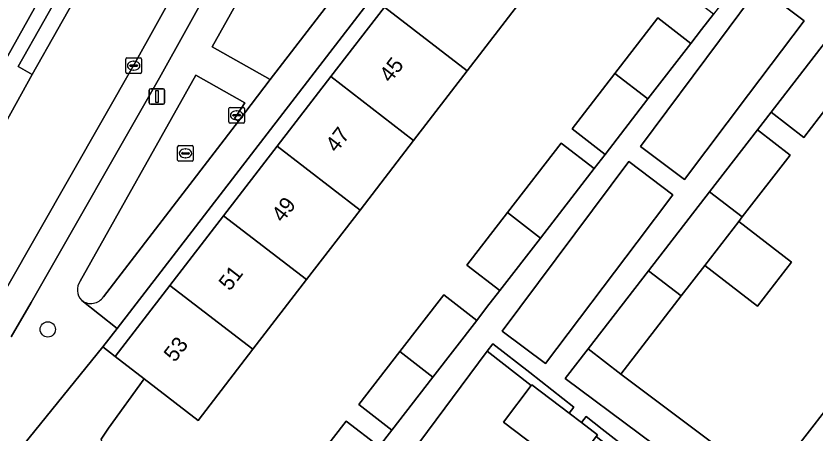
# Model space of a CAD drawing. Extents: x 159039 to 160102, y 381214 to 382524.
# Drawn here: x 159185.6 to 159236.7, y 381504.4 to 381531.1 of the extents above; entities that cross this region are included whole.
import ezdxf

# ---------------------------------------------------------------- set-up
doc = ezdxf.new("R2010")
doc.units = 0
for name, color, linetype in [('IMGEO_Boom', 7, 'Continuous'), ('IMGEO_Erf', 7, 'Continuous'), ('IMGEO_Groenvoorziening', 7, 'Continuous'), ('IMGEO_Kolk', 7, 'Continuous'), ('IMGEO_Lichtmast', 7, 'Continuous'), ('IMGEO_Pand', 7, 'Continuous'), ('IMGEO_Pand_nummerreeks', 7, 'Continuous'), ('IMGEO_Parkeervlak_open', 7, 'Continuous'), ('IMGEO_Rijbaan_lokaal_open', 7, 'Continuous'), ('IMGEO_Rioolput', 7, 'Continuous'), ('IMGEO_Voetpad_open', 7, 'Continuous')]:
    doc.layers.add(name, color=color, linetype=linetype)

msp = doc.modelspace()

# ---------------------------------------------------------------- linework, layer by layer
at = {"layer": 'IMGEO_Boom'}
msp.add_circle((159187.608, 381511.034), 0.489, dxfattribs=at)
at = {"layer": 'IMGEO_Erf'}
for points in [[(159225.401, 381554.424), (159192.033, 381511.095), (159191.13, 381509.922), (159191.91, 381509.302), (159195.414, 381513.848), (159198.846, 381518.299), (159202.279, 381522.752), (159205.711, 381527.204), (159209.143, 381531.656)], [(159212.926, 381513.239), (159215.038, 381511.61), (159215.669, 381512.427), (159216.508, 381513.514), (159214.396, 381515.142), (159216.994, 381518.504), (159220.431, 381522.952), (159222.542, 381521.324), (159223.24, 381522.227), (159221.129, 381523.855), (159223.869, 381527.4), (159226.617, 381530.956), (159228.727, 381529.33), (159229.415, 381530.221), (159230.179, 381531.21), (159228.069, 381532.836), (159230.742, 381536.295), (159233.31, 381539.618), (159235.418, 381537.992), (159236.286, 381539.116), (159234.178, 381540.742), (159237.678, 381545.272)], [(159173.453, 381507.955), (159176.296, 381513.115), (159179.604, 381518.88), (159180.292, 381520.169), (159180.696, 381520.785), (159188.162, 381534.124)], [(159217.857, 381532.034), (159214.429, 381527.58), (159211.001, 381523.125), (159207.573, 381518.67), (159204.145, 381514.215), (159200.717, 381509.76), (159197.216, 381505.211), (159193.761, 381507.875), (159191.482, 381504.708), (159191.012, 381504.016)], [(159233.651, 381501.109), (159237.416, 381505.981), (159241.32, 381511.034), (159245.252, 381516.123), (159243.127, 381517.765), (159246.961, 381522.727), (159250.649, 381527.499), (159252.774, 381525.857), (159256.666, 381530.894)], [(159237.43, 381525.232), (159235.947, 381523.313), (159233.855, 381524.929), (159232.982, 381523.799), (159235.074, 381522.183), (159232.015, 381518.224), (159231.797, 381517.942), (159235.165, 381515.341), (159232.985, 381512.52), (159229.618, 381515.122), (159228.111, 381513.172), (159224.253, 381508.179), (159231.589, 381502.66)], [(159203.239, 381500.702), (159206.684, 381505.16), (159208.797, 381503.531), (159209.615, 381504.59), (159207.503, 381506.221), (159210.121, 381509.609), (159212.926, 381513.239)], [(159232.559, 381496.471), (159231.636, 381497.192), (159230.56, 381498.032), (159229.092, 381496.063), (159228.937, 381495.854), (159225.509, 381498.452), (159222.066, 381501.061), (159222.241, 381501.296), (159223.764, 381503.337), (159222.679, 381504.184), (159221.149, 381502.131), (159220.97, 381501.891), (159216.745, 381505.093), (159218.518, 381507.433), (159215.703, 381509.632), (159210.768, 381503.013), (159203.221, 381492.897), (159214.857, 381484.15), (159222.203, 381478.451)]]:
    msp.add_lwpolyline(points, dxfattribs=at)
msp.add_arc((159182.126, 381523.448), 17.751, 60.4649, 199.9506, dxfattribs=at)
at = {"layer": 'IMGEO_Groenvoorziening'}
for points in [[(159211.449, 381539.519), (159211.235, 381539.689), (159211.37, 381539.861), (159211.764, 381540.468), (159206.227, 381543.609), (159198.115, 381529.116), (159201.832, 381527.029)], [(159235.973, 381530.774), (159233.084, 381532.954), (159230.557, 381529.518), (159225.496, 381522.744), (159228.311, 381520.62), (159232.419, 381526.063)], [(159227.577, 381519.646), (159224.766, 381521.767), (159216.66, 381510.915), (159219.428, 381508.846), (159225.296, 381516.623)], [(159218.428, 381508.265), (159216.072, 381510.105), (159215.703, 381509.632), (159218.518, 381507.433), (159218.556, 381507.483), (159220.944, 381505.673), (159221.248, 381506.063)], [(159224.253, 381508.179), (159222.161, 381509.796), (159220.696, 381507.9), (159230.193, 381500.805), (159231.589, 381502.66)], [(159223.048, 381504.657), (159222.031, 381505.451), (159221.736, 381505.073), (159222.762, 381504.295), (159222.679, 381504.184), (159223.764, 381503.337), (159223.859, 381503.465), (159224.594, 381502.908), (159224.857, 381503.245)]]:
    msp.add_lwpolyline(points, close=True, dxfattribs=at)
for points in [[(159199.8, 381524.351), (159199.555, 381524.522), (159199.686, 381524.729), (159200.197, 381525.522), (159197.07, 381527.304), (159189.668, 381514.114)], [(159191.162, 381513.114), (159199.8, 381524.351)], [(159189.761, 381512.901), (159189.786, 381512.882)]]:
    msp.add_lwpolyline(points, dxfattribs=at)
for centre, radius, start, end in [((159182.126, 381523.448), 17.751, 60.4649, 199.9506), ((159190.465, 381513.565), 0.968, 145.4294, 223.3391), ((159190.363, 381513.658), 0.967, 233.3618, 325.7789)]:
    msp.add_arc(centre, radius, start, end, dxfattribs=at)
at = {"layer": 'IMGEO_Kolk'}
for p, q in [((159192.593, 381527.479), (159192.593, 381528.331)), ((159192.668, 381528.405), (159193.52, 381528.405)), ((159193.594, 381528.331), (159193.594, 381527.479)), ((159192.852, 381527.899), (159192.852, 381527.911)), ((159193.29, 381527.862), (159192.892, 381527.862)), ((159192.895, 381527.948), (159193.293, 381527.948)), ((159193.081, 381528.185), (159193.106, 381528.185)), ((159193.336, 381527.911), (159193.336, 381527.899)), ((159193.52, 381527.405), (159192.668, 381527.405)), ((159193.104, 381527.625), (159193.079, 381527.625)), ((159199.186, 381524.303), (159199.186, 381525.155)), ((159199.261, 381525.229), (159200.113, 381525.229)), ((159200.187, 381525.155), (159200.187, 381524.303)), ((159199.445, 381524.723), (159199.445, 381524.735)), ((159199.883, 381524.686), (159199.485, 381524.686)), ((159199.488, 381524.772), (159199.886, 381524.772)), ((159199.674, 381525.009), (159199.699, 381525.009)), ((159199.929, 381524.735), (159199.929, 381524.723)), ((159200.113, 381524.229), (159199.261, 381524.229)), ((159199.697, 381524.449), (159199.672, 381524.449))]:
    msp.add_line(p, q, dxfattribs=at)
for points in [[(159192.593, 381527.479), (159192.593, 381528.331)], [(159192.668, 381528.405), (159193.52, 381528.405)], [(159193.594, 381528.331), (159193.594, 381527.479)], [(159193.52, 381527.405), (159192.668, 381527.405)], [(159199.186, 381524.303), (159199.186, 381525.155)], [(159199.261, 381525.229), (159200.113, 381525.229)], [(159200.187, 381525.155), (159200.187, 381524.303)], [(159200.113, 381524.229), (159199.261, 381524.229)]]:
    msp.add_lwpolyline(points, dxfattribs=at)
for centre, radius, start, end in [((159192.67, 381528.329), 0.0765, 91.552, 178.448), ((159192.67, 381528.329), 0.0765, 91.552, 178.448), ((159193.518, 381528.329), 0.0765, 1.552, 88.448), ((159193.518, 381528.329), 0.0765, 1.552, 88.448), ((159192.892, 381527.908), 0.0403, 85.8775, 175.7526), ((159192.889, 381527.898), 0.0366, 178.938, 274.7102), ((159193.293, 381527.905), 0.043, 264.8664, 352.4533), ((159193.297, 381527.91), 0.0386, 1.7309, 96.639), ((159192.67, 381527.481), 0.0765, 181.552, 268.448), ((159192.67, 381527.481), 0.0765, 181.552, 268.448), ((159193.518, 381527.481), 0.0765, 271.552, 358.448), ((159193.518, 381527.481), 0.0765, 271.552, 358.448), ((159199.263, 381525.153), 0.0765, 91.552, 178.448), ((159199.263, 381525.153), 0.0765, 91.552, 178.448), ((159200.111, 381525.153), 0.0765, 1.552, 88.448), ((159200.111, 381525.153), 0.0765, 1.552, 88.448), ((159199.485, 381524.732), 0.0403, 85.8775, 175.7526), ((159199.482, 381524.722), 0.0366, 178.938, 274.7102), ((159199.886, 381524.729), 0.043, 264.8664, 352.4533), ((159199.89, 381524.734), 0.0386, 1.7309, 96.639), ((159199.263, 381524.305), 0.0765, 181.552, 268.448), ((159199.263, 381524.305), 0.0765, 181.552, 268.448), ((159200.111, 381524.305), 0.0765, 271.552, 358.448), ((159200.111, 381524.305), 0.0765, 271.552, 358.448)]:
    msp.add_arc(centre, radius, start, end, dxfattribs=at)
for centre, major_axis, ratio, start_param, end_param in [((159193.08, 381527.905), (-0.387, 0.002), 0.722429, 4.712389, 7.853982), ((159193.105, 381527.905), (-0.39, 0.002), 0.717154, 1.570796, 4.712389), ((159199.673, 381524.729), (-0.387, 0.002), 0.722429, 4.712389, 7.853982), ((159199.698, 381524.729), (-0.39, 0.002), 0.717154, 1.570796, 4.712389)]:
    msp.add_ellipse(centre, major_axis=major_axis, ratio=ratio, start_param=start_param, end_param=end_param, dxfattribs=at)
at = {"layer": 'IMGEO_Lichtmast'}
for p, q in [((159194.088, 381525.533), (159194.088, 381526.333)), ((159194.088, 381526.333), (159194.088, 381525.533)), ((159194.188, 381526.433), (159194.978, 381526.433)), ((159194.978, 381526.433), (159194.188, 381526.433)), ((159195.078, 381526.333), (159195.078, 381525.533)), ((159195.078, 381525.533), (159195.078, 381526.333)), ((159194.978, 381525.433), (159194.188, 381525.433)), ((159194.188, 381525.433), (159194.978, 381525.433))]:
    msp.add_line(p, q, dxfattribs=at)
msp.add_lwpolyline([(159194.508, 381526.308), (159194.658, 381526.308), (159194.658, 381525.558), (159194.508, 381525.558), (159194.508, 381526.308)], dxfattribs=at)
for centre, start, end in [((159194.188, 381526.333), 90, 180), ((159194.188, 381526.333), 90, 180), ((159194.978, 381526.333), 0, 90), ((159194.978, 381526.333), 360, 90), ((159194.188, 381525.533), 180, 270), ((159194.188, 381525.533), 180, 270), ((159194.978, 381525.533), 270, 0), ((159194.978, 381525.533), 270, 0)]:
    msp.add_arc(centre, 0.1, start, end, dxfattribs=at)
at = {"layer": 'IMGEO_Pand'}
for points in [[(159217.857, 381532.034), (159212.574, 381536.106), (159209.143, 381531.656), (159214.429, 381527.58)], [(159211.001, 381523.125), (159214.429, 381527.58), (159209.143, 381531.656), (159205.711, 381527.204)], [(159228.727, 381529.33), (159226.617, 381530.956), (159223.869, 381527.4), (159225.979, 381525.774)], [(159241.687, 381526.801), (159239.781, 381528.274), (159237.689, 381529.891), (159233.855, 381524.929), (159235.947, 381523.313), (159237.43, 381525.232), (159239.335, 381523.759)], [(159207.573, 381518.67), (159211.001, 381523.125), (159205.711, 381527.204), (159202.279, 381522.752)], [(159225.979, 381525.774), (159223.869, 381527.4), (159221.129, 381523.855), (159223.24, 381522.227)], [(159235.074, 381522.183), (159232.982, 381523.799), (159229.923, 381519.841), (159232.015, 381518.224)], [(159207.573, 381518.67), (159202.279, 381522.752), (159198.846, 381518.299), (159204.145, 381514.215)], [(159219.106, 381516.876), (159222.542, 381521.324), (159220.431, 381522.952), (159216.994, 381518.504)], [(159231.797, 381517.942), (159232.015, 381518.224), (159229.923, 381519.841), (159226.019, 381514.788), (159228.111, 381513.172), (159229.618, 381515.122)], [(159219.106, 381516.876), (159216.994, 381518.504), (159214.396, 381515.142), (159216.508, 381513.514)], [(159195.414, 381513.848), (159200.717, 381509.76), (159204.145, 381514.215), (159198.846, 381518.299)], [(159231.797, 381517.942), (159229.618, 381515.122), (159232.985, 381512.52), (159235.165, 381515.341)], [(159228.111, 381513.172), (159226.019, 381514.788), (159222.161, 381509.796), (159224.253, 381508.179)], [(159195.414, 381513.848), (159191.91, 381509.302), (159193.761, 381507.875), (159197.216, 381505.211), (159200.717, 381509.76)], [(159215.038, 381511.61), (159212.926, 381513.239), (159210.121, 381509.609), (159212.234, 381507.981)], [(159212.234, 381507.981), (159210.121, 381509.609), (159207.503, 381506.221), (159209.615, 381504.59)], [(159220.944, 381505.673), (159218.556, 381507.483), (159218.518, 381507.433), (159216.745, 381505.093), (159220.97, 381501.891), (159221.149, 381502.131), (159222.679, 381504.184), (159222.762, 381504.295), (159221.736, 381505.073)], [(159237.416, 381505.981), (159233.651, 381501.109), (159235.088, 381500), (159239.061, 381496.992), (159241.375, 381500), (159242.785, 381501.832)], [(159208.797, 381503.531), (159206.684, 381505.16), (159203.239, 381500.702), (159204.147, 381500), (159205.351, 381499.07), (159206.069, 381500)]]:
    msp.add_lwpolyline(points, close=True, dxfattribs=at)
at = {"layer": 'IMGEO_Parkeervlak_open'}
for points in [[(159210.549, 381559.319), (159207.32, 381553.722), (159202.327, 381544.533), (159197.222, 381535.339), (159195.889, 381532.938), (159193.161, 381528.024), (159184.97, 381513.668), (159182.408, 381509.281)], [(159185.268, 381510.556), (159186.552, 381512.755), (159194.753, 381527.128), (159203.917, 381543.633), (159208.914, 381552.829), (159212.162, 381558.46), (159212.41, 381558.977)]]:
    msp.add_lwpolyline(points, dxfattribs=at)
at = {"layer": 'IMGEO_Rijbaan_lokaal_open'}
msp.add_lwpolyline([(159178.373, 381502.132), (159179.901, 381504.839), (159181.449, 381507.583), (159182.408, 381509.281), (159184.97, 381513.668), (159193.161, 381528.024), (159195.889, 381532.938), (159191.214, 381535.521), (159190.114, 381533.578), (159189.893, 381533.157), (159186.615, 381527.344), (159181.803, 381518.679), (159181.307, 381517.904), (159178.059, 381512.136), (159174.495, 381505.831), (159171.178, 381500)], dxfattribs=at)
at = {"layer": 'IMGEO_Rioolput'}
for p, q in [((159195.91, 381521.87), (159195.91, 381522.722)), ((159195.985, 381522.796), (159196.837, 381522.796)), ((159196.911, 381522.722), (159196.911, 381521.87)), ((159196.169, 381522.29), (159196.169, 381522.302)), ((159196.607, 381522.253), (159196.209, 381522.253)), ((159196.212, 381522.339), (159196.61, 381522.339)), ((159196.398, 381522.576), (159196.423, 381522.576)), ((159196.653, 381522.302), (159196.653, 381522.29)), ((159196.837, 381521.796), (159195.985, 381521.796)), ((159196.421, 381522.016), (159196.396, 381522.016))]:
    msp.add_line(p, q, dxfattribs=at)
for points in [[(159195.91, 381521.87), (159195.91, 381522.722)], [(159195.985, 381522.796), (159196.837, 381522.796)], [(159196.911, 381522.722), (159196.911, 381521.87)], [(159196.837, 381521.796), (159195.985, 381521.796)]]:
    msp.add_lwpolyline(points, dxfattribs=at)
for centre, radius, start, end in [((159195.987, 381522.72), 0.0765, 91.552, 178.448), ((159195.987, 381522.72), 0.0765, 91.552, 178.448), ((159196.835, 381522.72), 0.0765, 1.552, 88.448), ((159196.835, 381522.72), 0.0765, 1.552, 88.448), ((159196.209, 381522.299), 0.0403, 85.8775, 175.7526), ((159196.206, 381522.289), 0.0366, 178.938, 274.7102), ((159196.61, 381522.296), 0.043, 264.8664, 352.4533), ((159196.614, 381522.301), 0.0386, 1.7309, 96.639), ((159195.987, 381521.872), 0.0765, 181.552, 268.448), ((159195.987, 381521.872), 0.0765, 181.552, 268.448), ((159196.835, 381521.872), 0.0765, 271.552, 358.448), ((159196.835, 381521.872), 0.0765, 271.552, 358.448)]:
    msp.add_arc(centre, radius, start, end, dxfattribs=at)
for centre, major_axis, ratio, start_param, end_param in [((159196.397, 381522.296), (-0.387, 0.002), 0.722429, 4.712389, 7.853982), ((159196.422, 381522.296), (-0.39, 0.002), 0.717154, 1.570796, 4.712389)]:
    msp.add_ellipse(centre, major_axis=major_axis, ratio=ratio, start_param=start_param, end_param=end_param, dxfattribs=at)
at = {"layer": 'IMGEO_Voetpad_open'}
for points in [[(159189.668, 381514.114), (159197.07, 381527.304), (159200.197, 381525.522), (159199.686, 381524.729), (159199.555, 381524.522), (159199.8, 381524.351), (159201.832, 381527.029), (159198.115, 381529.116), (159206.227, 381543.609), (159211.764, 381540.468), (159211.37, 381539.861), (159211.235, 381539.689), (159211.449, 381539.519), (159213.388, 381541.973), (159207.287, 381545.497), (159215.578, 381560.327), (159215.764, 381560.612), (159219.15, 381565.78), (159220.263, 381570.498)], [(159202.211, 381559.115), (159197.939, 381551.409), (159196.616, 381548.975), (159190.876, 381538.892), (159188.162, 381534.124), (159180.696, 381520.785), (159180.292, 381520.169), (159179.604, 381518.88), (159176.296, 381513.115), (159173.453, 381507.955), (159172.813, 381506.792), (159171.954, 381505.356), (159168.747, 381500)], [(159212.41, 381558.977), (159212.162, 381558.46), (159208.914, 381552.829), (159203.917, 381543.633), (159194.753, 381527.128), (159186.552, 381512.755), (159185.268, 381510.556)], [(159223.765, 381555.465), (159213.388, 381541.973), (159211.449, 381539.519), (159201.832, 381527.029), (159199.8, 381524.351), (159191.162, 381513.114)], [(159189.786, 381512.882), (159192.033, 381511.095), (159225.401, 381554.424)], [(159239.784, 381543.644), (159236.286, 381539.116), (159235.418, 381537.992), (159232.851, 381534.669), (159230.179, 381531.21), (159229.415, 381530.221), (159228.727, 381529.33), (159225.979, 381525.774), (159223.24, 381522.227), (159222.542, 381521.324), (159219.106, 381516.876), (159216.508, 381513.514), (159215.669, 381512.427), (159215.038, 381511.61), (159212.234, 381507.981), (159209.615, 381504.59), (159208.797, 381503.531)], [(159142.37, 381448.941), (159146.11, 381455.538), (159151.125, 381464.42), (159154.371, 381470.177), (159154.48, 381470.371), (159155.72, 381472.568), (159158.808, 381478.041), (159162.975, 381485.583), (159169.891, 381497.722), (159171.178, 381500), (159174.495, 381505.831), (159178.059, 381512.136), (159181.307, 381517.904), (159181.803, 381518.679), (159186.615, 381527.344), (159185.709, 381527.855), (159188.987, 381533.668), (159189.893, 381533.157), (159190.114, 381533.578), (159191.214, 381535.521), (159191.522, 381536.074)], [(159230.193, 381500.805), (159220.696, 381507.9), (159222.161, 381509.796), (159226.019, 381514.788), (159229.923, 381519.841), (159232.982, 381523.799), (159233.855, 381524.929), (159237.689, 381529.891)], [(159181.502, 381496.086), (159183.613, 381499.573), (159183.847, 381500), (159184.764, 381501.604), (159185.68, 381503.207), (159191.13, 381509.922), (159192.033, 381511.095), (159189.786, 381512.882), (159189.761, 381512.901)], [(159222.203, 381478.451), (159214.857, 381484.15), (159203.221, 381492.897), (159201.517, 381494.178), (159193.333, 381500), (159192.473, 381500.612), (159191.957, 381501.003), (159191.931, 381501.023), (159191.012, 381504.016), (159191.482, 381504.708), (159193.761, 381507.875), (159191.91, 381509.302), (159191.13, 381509.922), (159185.68, 381503.207), (159190.18, 381500), (159191.411, 381499.122), (159197.785, 381494.58)], [(159210.768, 381503.013), (159215.703, 381509.632), (159216.072, 381510.105), (159218.428, 381508.265), (159221.248, 381506.063), (159220.944, 381505.673), (159221.736, 381505.073), (159222.031, 381505.451), (159223.048, 381504.657), (159224.857, 381503.245)]]:
    msp.add_lwpolyline(points, dxfattribs=at)
for points in [[(159189.893, 381533.157), (159188.987, 381533.668), (159185.709, 381527.855), (159186.615, 381527.344)], [(159232.419, 381526.063), (159228.311, 381520.62), (159225.496, 381522.744), (159230.557, 381529.518), (159233.084, 381532.954), (159235.973, 381530.774)], [(159227.577, 381519.646), (159225.296, 381516.623), (159219.428, 381508.846), (159216.66, 381510.915), (159224.766, 381521.767)]]:
    msp.add_lwpolyline(points, close=True, dxfattribs=at)
for centre, radius, start, end in [((159190.465, 381513.565), 0.968, 145.4294, 223.3391), ((159190.363, 381513.658), 0.967, 233.3618, 325.7789)]:
    msp.add_arc(centre, radius, start, end, dxfattribs=at)

# ---------------------------------------------------------------- texts
at = {"layer": 'IMGEO_Pand_nummerreeks'}
for s, p in [('45', (159209.513, 381526.762)), ('47', (159206.066, 381522.291)), ('49', (159202.62, 381517.821)), ('51', (159199.242, 381513.44)), ('53', (159195.727, 381508.88))]:
    msp.add_text(s, height=1, rotation=52.3705, dxfattribs=at).set_placement(p)

doc.saveas('drawing.dxf')
